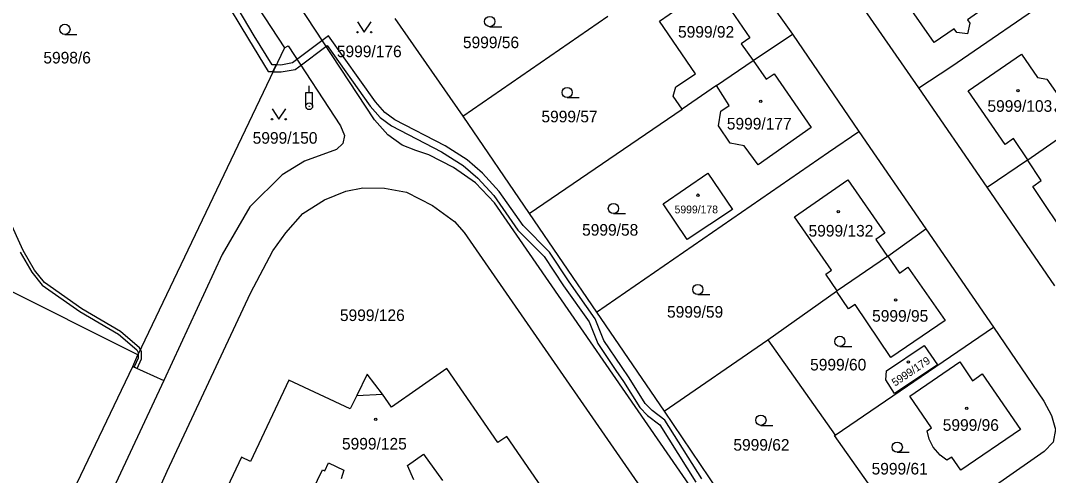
# Model space of a CAD drawing. Extents: x -644096 to -634268, y -1141430 to -1133463.
# Drawn here: x -639627.9 to -639477.5, y -1139071.2 to -1139004.5 of the extents above; entities that cross this region are included whole.
import ezdxf

# ---------------------------------------------------------------- set-up
doc = ezdxf.new("R2010")
doc.units = 0
for name, color, linetype in [('B_Hranice _3D', 7, 'Continuous'), ('M_Svah_Nasyp', 7, 'Continuous'), ('M_Svah_Zarez', 7, 'Continuous'), ('SOXXXXXX_Koleje_Osa_KOOR', 7, 'Continuous'), ('svrsek_osa_sjezdy', 7, 'Continuous'), ('svrsek_osa_terminal_VRT', 7, 'Continuous'), ('svrsek_osa_VRT', 7, 'Continuous'), ('terminal_VRT', 7, 'Continuous')]:
    doc.layers.add(name, color=color, linetype=linetype)

msp = doc.modelspace()

# ---------------------------------------------------------------- linework, layer by layer
at = {"layer": 'B_Hranice _3D'}
msp.add_lwpolyline([(-639600.53, -1138995.09), (-639603.51, -1138990.32), (-639607.85, -1138983.54), (-639611.88, -1138977.76), (-639615.28, -1138972.69), (-639622.63, -1138961.21), (-639625.3, -1138957.2), (-639625.82, -1138958.23), (-639623.47, -1138961.75), (-639616.12, -1138973.23), (-639612.7, -1138978.32), (-639608.69, -1138984.1), (-639604.35, -1138990.86), (-639601.39, -1138995.61), (-639598.49, -1139000.65), (-639594.57, -1139007.27), (-639591.7, -1139011.98), (-639590.98, -1139012.01), (-639590.51, -1139011.03), (-639591.12, -1139011), (-639593.71, -1139006.75), (-639597.63, -1139000.15)], close=True, dxfattribs=at)
for points in [[(-639528.2, -1139071.66), (-639533.64, -1139063.05), (-639535.51, -1139061.66), (-639536.49, -1139060.6), (-639538.85, -1139056.88), (-639539.98, -1139055.22), (-639542.54, -1139051.39), (-639543.81, -1139048.2), (-639547.65, -1139042.81), (-639550.53, -1139038.47), (-639554.35, -1139034.57), (-639557.87, -1139029.56), (-639560.32, -1139026.9), (-639562.57, -1139024.95), (-639565.8, -1139022.89), (-639573.13, -1139019.09), (-639574.63, -1139017.99), (-639575.96, -1139016.44), (-639582.85, -1139006.75), (-639587.73, -1139010.45), (-639588.13, -1139010.75), (-639589.85, -1139011.06), (-639590.36, -1139011.04), (-639590.51, -1139011.03), (-639590.98, -1139012.01), (-639590.83, -1139012.02), (-639589.79, -1139012.06), (-639587.71, -1139011.69), (-639587.19, -1139011.3), (-639583.07, -1139008.17), (-639576.74, -1139017.06), (-639575.31, -1139018.73), (-639573.65, -1139019.95), (-639566.3, -1139023.75), (-639563.17, -1139025.75), (-639561.02, -1139027.62), (-639558.65, -1139030.18), (-639555.13, -1139035.21), (-639551.31, -1139039.11), (-639548.47, -1139043.37), (-639544.69, -1139048.68), (-639543.44, -1139051.85), (-639540.8, -1139055.78), (-639539.69, -1139057.42), (-639537.29, -1139061.22), (-639536.19, -1139062.4), (-639534.38, -1139063.75), (-639529.08, -1139072.14)], [(-639628, -1139038.46), (-639626.28, -1139041.37), (-639624.78, -1139043.28), (-639619.23, -1139047.16), (-639613.58, -1139050.46), (-639610.92, -1139052.77), (-639610.7, -1139053.17), (-639610.7, -1139053.34), (-639610.7, -1139053.96), (-639611.31, -1139055.26), (-639610.85, -1139055.47), (-639610.2, -1139054.08), (-639610.2, -1139053.05), (-639610.39, -1139052.69), (-639610.52, -1139052.45), (-639613.28, -1139050.06), (-639618.97, -1139046.74), (-639624.44, -1139042.92), (-639625.86, -1139041.09), (-639627.56, -1139038.22), (-639631.9, -1139028.72)]]:
    msp.add_lwpolyline(points, dxfattribs=at)
at = {"layer": 'M_Svah_Nasyp'}
msp.add_line((-639578.73, -1139059.45), (-639574.97, -1139059.24), dxfattribs=at)
at = {"layer": 'M_Svah_Zarez'}
for centre in [(-639481.95, -1139014.79), (-639519.59, -1139016.37), (-639528.79, -1139030.11), (-639508.26, -1139032.51), (-639499.86, -1139045.46), (-639497.99, -1139054.53), (-639489.46, -1139061.33), (-639575.95, -1139062.93)]:
    msp.add_circle(centre, 0.175, dxfattribs=at)
at = {"layer": 'SOXXXXXX_Koleje_Osa_KOOR'}
for p, q in [((-639586.18, -1139015.08), (-639585.18, -1139015.08)), ((-639586.18, -1139017.08), (-639586.18, -1139015.08)), ((-639585.68, -1139015.08), (-639585.68, -1139014.08)), ((-639585.18, -1139017.08), (-639585.18, -1139015.08))]:
    msp.add_line(p, q, dxfattribs=at)
for radius in [0.5, 0.0303]:
    msp.add_circle((-639585.68, -1139017.08), radius, dxfattribs=at)
at = {"layer": 'svrsek_osa_sjezdy'}
for p, q in [((-639559.26, -1139005.43), (-639557.51, -1139005.43)), ((-639621.43, -1139006.57), (-639619.68, -1139006.57)), ((-639547.92, -1139015.82), (-639546.17, -1139015.82)), ((-639541.16, -1139032.81), (-639539.41, -1139032.81)), ((-639528.8, -1139044.68), (-639527.05, -1139044.68)), ((-639508.02, -1139052.27), (-639506.27, -1139052.27)), ((-639519.57, -1139063.82), (-639517.82, -1139063.82)), ((-639499.62, -1139067.77), (-639497.87, -1139067.77))]:
    msp.add_line(p, q, dxfattribs=at)
for points in [[(-639578.61, -1139004.74), (-639577.61, -1139006.24), (-639576.61, -1139004.74)], [(-639591.12, -1139017.48), (-639590.12, -1139018.98), (-639589.12, -1139017.48)]]:
    msp.add_lwpolyline(points, dxfattribs=at)
for centre, radius in [((-639559.26, -1139004.68), 0.75), ((-639621.43, -1139005.82), 0.75), ((-639578.61, -1139006.24), 0.1), ((-639576.61, -1139006.24), 0.1), ((-639547.92, -1139015.07), 0.75), ((-639591.12, -1139018.98), 0.1), ((-639589.12, -1139018.98), 0.1), ((-639541.16, -1139032.06), 0.75), ((-639528.8, -1139043.93), 0.75), ((-639508.02, -1139051.52), 0.75), ((-639519.57, -1139063.07), 0.75), ((-639499.62, -1139067.02), 0.75)]:
    msp.add_circle(centre, radius, dxfattribs=at)
at = {"layer": 'svrsek_osa_terminal_VRT'}
msp.add_arc((-642050.26, -1145189.6), 8802.25, 41.413152, 75.317049, dxfattribs=at)
at = {"layer": 'terminal_VRT'}
for p, q in [((-639624.22, -1138955.04), (-639589.31, -1139008.51)), ((-639525.01, -1138992.2), (-639514.94, -1139006.53)), ((-639496.47, -1139014.41), (-639506.22, -1139000.25)), ((-639573.14, -1139004.21), (-639563.2, -1139018.54)), ((-639563.2, -1139018.54), (-639541.97, -1139003.89)), ((-639520.72, -1139010.36), (-639514.94, -1139006.53)), ((-639514.94, -1139006.53), (-639505.24, -1139020.8)), ((-639589.31, -1139008.51), (-639610.76, -1139053.47)), ((-639526.08, -1139014.06), (-639520.72, -1139010.36)), ((-639526.08, -1139014.06), (-639531.11, -1139017.53)), ((-639486.45, -1139028.96), (-639496.47, -1139014.41)), ((-639553.47, -1139032.79), (-639531.11, -1139017.53)), ((-639563.2, -1139018.54), (-639553.47, -1139032.79)), ((-639505.24, -1139020.8), (-639495.42, -1139035.03)), ((-639480.51, -1139024.91), (-639474.39, -1139020.68)), ((-639486.45, -1139028.96), (-639480.57, -1139024.95)), ((-639480.57, -1139024.95), (-639480.51, -1139024.91)), ((-639610.76, -1139053.47), (-639660.87, -1139028.37)), ((-639476.54, -1139043.39), (-639486.45, -1139028.96)), ((-639553.47, -1139032.79), (-639543.63, -1139047.23)), ((-639500.98, -1139039.02), (-639495.42, -1139035.03)), ((-639495.42, -1139035.03), (-639485.55, -1139049.46)), ((-639501.07, -1139039.08), (-639508.4, -1139044.13)), ((-639501.07, -1139039.08), (-639500.98, -1139039.02)), ((-639518.55, -1139051.31), (-639508.49, -1139044.19)), ((-639508.49, -1139044.19), (-639508.4, -1139044.13)), ((-639543.63, -1139047.23), (-639533.75, -1139061.72)), ((-639508.7, -1139065.26), (-639485.55, -1139049.46)), ((-639533.75, -1139061.72), (-639518.55, -1139051.31)), ((-639518.55, -1139051.31), (-639508.7, -1139065.26)), ((-639611.48, -1139055.18), (-639610.76, -1139053.47)), ((-639628.79, -1139091.38), (-639611.48, -1139055.18)), ((-639611.48, -1139055.18), (-639606.97, -1139057.27)), ((-639606.97, -1139057.27), (-639623.91, -1139093.59)), ((-639533.75, -1139061.72), (-639525.84, -1139073.47))]:
    msp.add_line(p, q, dxfattribs=at)
for points in [[(-639491.77, -1138990.46), (-639489.83, -1138993.33), (-639491.8, -1138994.53), (-639486.4, -1139002.36), (-639489.36, -1139004.41), (-639489, -1139004.93), (-639489.34, -1139006.47), (-639490.89, -1139006.27), (-639491.27, -1139005.74), (-639494.22, -1139007.76), (-639499.61, -1138999.92), (-639498.37, -1138999.08), (-639500.31, -1138996.29)], [(-639496.47, -1139014.41), (-639491.8, -1139011.3), (-639460.46, -1138989.8)], [(-639525.84, -1139073.47), (-639527.05, -1139074.38), (-639528.17, -1139075.25), (-639558.54, -1139031.23), (-639561.34, -1139028.29), (-639564.54, -1139026.04), (-639568.19, -1139024.2), (-639570.08, -1139023.56), (-639572.05, -1139022.77), (-639574.19, -1139021.25), (-639576.12, -1139019.06), (-639592.26, -1138994.46)], [(-639531.11, -1139017.53), (-639532.43, -1139015.61), (-639532.02, -1139014.24), (-639529.13, -1139012.32), (-639534.42, -1139004.61), (-639531.58, -1139002.66), (-639526.57, -1138999.22), (-639521.21, -1139007.07), (-639522.45, -1139007.93), (-639520.72, -1139010.36)], [(-639589.31, -1139008.51), (-639588.75, -1139008.22), (-639581.08, -1139019.94), (-639580.49, -1139021.39), (-639580.76, -1139022.55), (-639581.66, -1139023.4), (-639586.37, -1139025.12), (-639589.62, -1139027.15), (-639594.35, -1139031.82), (-639598.4, -1139038.82), (-639606.97, -1139057.27)], [(-639520.72, -1139010.36), (-639518.79, -1139013.14), (-639517.63, -1139012.35), (-639512.24, -1139020.22), (-639519.99, -1139025.68), (-639522.01, -1139022.86), (-639524.07, -1139022.47), (-639525.79, -1139019.96), (-639525.42, -1139017.81), (-639524.2, -1139016.97), (-639526.08, -1139014.06)], [(-639480.51, -1139024.91), (-639482.6, -1139021.8), (-639483.85, -1139022.68), (-639489.25, -1139014.83), (-639481.44, -1139009.44), (-639479.09, -1139012.86), (-639477.74, -1139013.1), (-639475.78, -1139015.88), (-639476.04, -1139017.26), (-639476.57, -1139017.62), (-639474.39, -1139020.68)], [(-639471.77, -1139018.87), (-639466.89, -1139026.24), (-639468.08, -1139027.04), (-639466.05, -1139030.01), (-639466.39, -1139031.5), (-639474.34, -1139036.96), (-639479.8, -1139028.82), (-639478.54, -1139027.98), (-639480.57, -1139024.95)], [(-639543.63, -1139047.23), (-639509.69, -1139023.82), (-639505.24, -1139020.8)], [(-639533.9, -1139031.36), (-639527.35, -1139026.88), (-639523.71, -1139032.23), (-639530.36, -1139036.61), (-639533.9, -1139031.36)], [(-639508.4, -1139044.13), (-639510.07, -1139041.67), (-639509.25, -1139041.11), (-639514.65, -1139033.27), (-639506.83, -1139027.87), (-639501.44, -1139035.67), (-639502.77, -1139036.58), (-639501.07, -1139039.08)], [(-639610.81, -1139091.89), (-639608.81, -1139087.45), (-639609.98, -1139086.8), (-639611.04, -1139085.89), (-639611.87, -1139084.49), (-639612.09, -1139083.09), (-639606.47, -1139070.54), (-639594.26, -1139044.48), (-639591.01, -1139038.26), (-639589.12, -1139035.61), (-639586.59, -1139032.8), (-639583.43, -1139030.8), (-639580.33, -1139029.52), (-639577.84, -1139029.04), (-639574.64, -1139029.07), (-639571.45, -1139029.67), (-639567.61, -1139031.61), (-639564.42, -1139033.98), (-639563.01, -1139035.56), (-639531.07, -1139081.78)], [(-639500.98, -1139039.02), (-639499.27, -1139041.55), (-639498.05, -1139040.64), (-639492.62, -1139048.47), (-639500.54, -1139053.9), (-639505.78, -1139046.12), (-639506.73, -1139046.76), (-639508.49, -1139044.19)], [(-639485.55, -1139049.46), (-639478.15, -1139060.27), (-639477.05, -1139062.37), (-639476.47, -1139064.43), (-639476.81, -1139066.27), (-639478.12, -1139067.66), (-639497.59, -1139081.26)], [(-639501.19, -1139055.84), (-639495.69, -1139052.12), (-639493.72, -1139054.97), (-639500, -1139059.16), (-639501.29, -1139057.15), (-639501.19, -1139055.84)], [(-639547.58, -1139078.79), (-639556.76, -1139065.45), (-639558.05, -1139066.34), (-639565.54, -1139055.47), (-639573.63, -1139061.14), (-639574.97, -1139059.24)], [(-639492.34, -1139068.94), (-639493.34, -1139068.18), (-639494.37, -1139067.03), (-639494.96, -1139065.83), (-639495.26, -1139064.63), (-639494.6, -1139064.18), (-639497.77, -1139059.54), (-639490.48, -1139054.54), (-639488.61, -1139057.28), (-639487.17, -1139056.29), (-639481.59, -1139064.41), (-639490.33, -1139070.37), (-639491.65, -1139068.46), (-639492.34, -1139068.94)], [(-639574.97, -1139059.24), (-639577.2, -1139056.32), (-639578.73, -1139059.45), (-639579.68, -1139061.42), (-639588.64, -1139057.22), (-639594.26, -1139069.12), (-639595.6, -1139068.49), (-639602.54, -1139083.27)], [(-639508.7, -1139065.26), (-639508.83, -1139065.29), (-639497.59, -1139081.26)], [(-639585.18, -1139073.37), (-639583.75, -1139070.34), (-639583.41, -1139070.5), (-639582.86, -1139069.33), (-639580.61, -1139070.39), (-639581.02, -1139071.67)], [(-639570.37, -1139071.8), (-639571.3, -1139069.71), (-639568.93, -1139068.03), (-639566.18, -1139071.92)]]:
    msp.add_lwpolyline(points, dxfattribs=at)

# ---------------------------------------------------------------- texts
at = {"layer": 'svrsek_osa_VRT'}
for s, height, p in [('5999/92', 1.7, (-639531.7, -1139007.04)), ('5999/56', 1.7, (-639563.18, -1139008.58)), ('5998/6', 1.7, (-639624.58, -1139010.82)), ('5999/176', 1.7, (-639581.63, -1139009.9)), ('5999/103', 1.7, (-639486.42, -1139017.9)), ('5999/57', 1.7, (-639551.69, -1139019.44)), ('5999/177', 1.7, (-639524.56, -1139020.49)), ('5999/150', 1.7, (-639593.95, -1139022.57)), ('5999/178', 1.14, (-639532.21, -1139032.77)), ('5999/58', 1.7, (-639545.74, -1139036.04)), ('5999/132', 1.7, (-639512.6, -1139036.17)), ('5999/126', 1.7, (-639581.18, -1139048.54)), ('5999/59', 1.7, (-639533.31, -1139048.05)), ('5999/95', 1.7, (-639503.3, -1139048.64)), ('5999/60', 1.7, (-639512.37, -1139055.78)), ('5999/96', 1.7, (-639492.96, -1139064.62)), ('5999/125', 1.7, (-639580.88, -1139067.36)), ('5999/62', 1.7, (-639523.6, -1139067.53)), ('5999/61', 1.7, (-639503.37, -1139071.02))]:
    msp.add_text(s, height=height, dxfattribs=at).set_placement(p)
msp.add_text('5999/179', height=1.14, rotation=34, dxfattribs=at).set_placement((-639499.94, -1139058.16))

doc.saveas('drawing.dxf')
